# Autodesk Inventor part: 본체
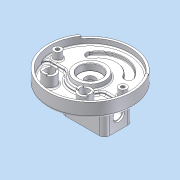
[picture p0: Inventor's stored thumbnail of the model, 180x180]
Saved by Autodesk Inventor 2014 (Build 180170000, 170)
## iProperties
Company: 한국ATC센터
Created: 2015-04
Part Number: 본체
Document SubType Name: Modeling
Designer: KYOUNG IL JANG
Density: 1 g/cm^3
Material: 일반
Mass: 494.771 g
Surface Area: 1387.38 cm^2
Volume: 494.771 cm^3
Appearance: 매끄러움 - 흰색
Author: KYOUNG IL JANG
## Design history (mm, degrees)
sketch "스케치1"
  geometry: L1 (-59, -19)-(-59, 19); L2 (59, 19)-(59, -19); L3 (-41, 19)-(-41, -19); L4 (41, -19)-(41, 19); L5 (38.527, 33.023)-(55.442, 39.179); L6 (-38.527, 33.023)-(-55.442, 39.179); C1 r 90 at (0, 0); C2 r 95 at (0, 0); A1 r 59 centre (0, 19) between (59, 19) and (-59, 19); A2 r 59 centre (0, -19) between (-59, -19) and (59, -19); A3 r 41 centre (0, -19) between (-41, -19) and (41, -19); A4 r 41 centre (0, 19) between (41, 19) and (-41, 19); 2 further points
  constraints: 12 end point, 12 point on circle, 6 centre point, 4 tangent, 2 parallel, 2 point on line, 1 coincident, 1 horizontal alignment, 1 midpoint, 1 vertical, 1 vertical alignment, 3 other
  dimensions: "d2" = 180 diameter of C1; "d3" = 156 dimension on A2 A1; "d4" = 118 distance between parallel lines of L2 L1; "d5" = 18 distance between parallel lines of L2 L4; "d8" = 190 diameter of C2; "d124" = 110 deg dimension on A1.centre point (0, 0) L5.end; "d125" = 140 deg angle of L5 L6
extrude "돌출1" new body sketch "스케치1" distance "d6" = 14; taper "d7" = 0 deg
extrude "돌출2" join sketch "스케치1" distance "d9" = 13; taper "d10" = 0 deg
extrude "돌출3" cut sketch "스케치1" distance "d11" = 7; taper "d12" = 0 deg
sketch "스케치2"
  geometry: C1 r 11.5 at (0, 0); 1 further point
  constraints: 1 centre point, 1 coincident
  dimensions: "d13" = 23 diameter of C1
extrude "돌출4" cut sketch "스케치2" stored distance "d14" = 7; taper "d15" = 0 deg
fillet "모깎기1"
fillet "모깎기2"
sketch "스케치3"
  geometry: L1 (-73.724, 51.622)-(-77.819, 54.49); L2 (73.724, 51.622)-(77.819, 54.49); L3 (0, 0)-(0, -90); A1 r 95 centre (0, 0) between (-77.819, 54.49) and (77.819, 54.49) reference; A2 r 90 centre (0, 0) between (-73.724, 51.622) and (73.724, 51.622) reference; 1 further point
  constraints: 6 end point, 5 point on circle, 1 point on line, 1 vertical, 1 other
  dimensions: "d16" = 250 deg dimension on L2 L1
extrude "돌출5" join sketch "스케치3" distance "d17" = 5; taper "d18" = 0 deg
hole "구멍1" diameter "d21" = 50; stored, may be unused: countersink angle "d25" = 90 deg, drill point angle "d27" = 0 deg; dims "d19" = 10, "d20" = 10, "d22" = 6, "d23" = 4, "d24" = 2, "d26" = 5
fillet "모깎기3" dims "d28" = 0.3
fillet "모깎기5" dims "d30" = 3
sketch "스케치4"
  geometry: C1 r 35 at (0, 0); C2 r 25 at (0, 0); 1 further point
  constraints: 2 centre point, 1 coincident
  dimensions: "d32" = 70 diameter of C1 (derived); "d36" = 10 radial gap between concentric circles of C1 C2
extrude "돌출6" join sketch "스케치4" distance "d33" = 10; taper "d34" = 0 deg
feature "면 기울기2" dims angle "d37" = 10 deg
chamfer "모따기1" distance "d39" = 1; stored, may be unused: second distance "d40" = 2, angle "d41" = 45 deg
fillet "모깎기7" dims "d42" = 5
sketch "스케치5"
  geometry: L1 (-40.249, -12)-(-89.196, -12); L2 (40.249, -12)-(89.196, -12); A1 r 90 centre (0, 0) between (-89.196, -12) and (89.196, -12) reference; A2 r 42 centre (0, 0) between (-40.249, -12) and (40.249, -12); 1 further point
  constraints: 4 end point, 4 point on circle, 1 centre point, 1 collinear, 1 horizontal, 1 point on line
  dimensions: "d43" = 48 radial gap between concentric circles of A1 A2; "d44" = 12 distance from line of point (0, 0) L1
extrude "돌출7" cut sketch "스케치5" stored distance "d45" = 10; taper "d46" = 0 deg
fillet "모깎기8" dims "d47" = 10
chamfer "모따기2" distance "d49" = 1; stored, may be unused: second distance "d50" = 2, angle "d51" = 45 deg
sketch "스케치8"
  geometry: C1 r 9 at (74, 0); C2 r 9 at (-74, 0); A1 r 74 centre (0, 0) between (74, 0) and (-74, 0); 1 further point
  constraints: 3 centre point, 2 horizontal alignment, 2 point on circle, 1 coincident, 1 equal radius
  dimensions: "d64" = 18 diameter of C1; "d65" = 148 diameter of A1
extrude "돌출9" join sketch "스케치8" stored distance "d66" = 5; taper "d67" = 0 deg
sketch "스케치11"
  geometry: C1 r 15 at (40, -52); C2 r 15 at (-40, -52); 1 further point
  constraints: 2 centre point, 1 equal radius, 1 horizontal alignment
  dimensions: "d82" = 52 vertical distance of point (0, 0) C1.centre; "d83" = 30 diameter of C1; "d84" = 80 distance of C2.centre C1.centre; "d85" = 40 horizontal distance of point (0, 0) C1.centre (= 0.5 x d84)
extrude "돌출10" join sketch "스케치11" stored distance "d86" = 10; taper "d87" = 0 deg
node "구멍3"
node "구멍5"
hole "구멍6" diameter "d92" = 20; stored, may be unused: countersink angle "d96" = 90 deg, drill point angle "d98" = 118 deg; dims "d90" = 10, "d91" = 10, "d93" = 6, "d94" = 4, "d95" = 2, "d97" = 8
hole "구멍7" diameter "d101" = 20; stored, may be unused: countersink angle "d105" = 90 deg, drill point angle "d107" = 118 deg; dims "d99" = 10, "d100" = 10, "d102" = 6, "d103" = 4, "d104" = 2, "d106" = 8
fillet "모깎기13" dims "d108" = 3
sketch "스케치13"
  geometry: L1 (-20.252, -58)-(-26, -58); L2 (-42, -58)-(-47.748, -58); L3 (-20.252, -46)-(-26, -46); L4 (-42, -46)-(-47.748, -46); L5 (-108, -65.748)-(-108, -60); L6 (-108, -44)-(-108, -38.252); L7 (-120, -44)-(-120, -38.252); L8 (-120, -60)-(-120, -65.748); A1 r 15 centre (-34, -52) between (-20.252, -58) and (-47.748, -58) reference; A2 r 10 centre (-34, -52) between (-26, -58) and (-42, -58) reference; A3 r 15 centre (-114, -52) between (-108, -65.748) and (-108, -38.252) reference; A4 r 10 centre (-114, -52) between (-108, -60) and (-108, -44) reference; 1 further point
  constraints: 16 end point, 16 point on circle, 3 equal length, 3 point on line, 2 collinear, 1 horizontal, 1 perpendicular
  dimensions: "d114" = 12 distance between parallel lines of L4 L2; "d115" = 6 distance from line of A1.centre L2 (= 0.5 x d114); "d116" = 12 distance between parallel lines of L8 L5 (= d114); "d117" = 6 distance from line of A3.centre L5 (= d115)
extrude "돌출12" join sketch "스케치13" distance "d118" = 3; taper "d119" = 0 deg
fillet "모깎기14" dims "d120" = 1
sketch "스케치14"
  geometry: L1 (23, 32.5)-(-53, 32.5); L2 (-65, 20.5)-(-65, -20.5); L3 (-53, -32.5)-(23, -32.5); L4 (35, -20.5)-(35, 20.5); L5 (30, 20.5)-(30, -20.5); L6 (23, -27.5)-(-53, -27.5); L7 (-60, -20.5)-(-60, 20.5); L8 (-53, 27.5)-(23, 27.5); A1 r 12 centre (-53, -20.5) between (-65, -20.5) and (-53, -32.5); A2 r 12 centre (-53, 20.5) between (-53, 32.5) and (-65, 20.5); A3 r 12 centre (23, 20.5) between (35, 20.5) and (23, 32.5); A4 r 12 centre (23, -20.5) between (23, -32.5) and (35, -20.5); A5 r 7 centre (23, -20.5) between (23, -27.5) and (30, -20.5); A6 r 7 centre (-53, -20.5) between (-60, -20.5) and (-53, -27.5); A7 r 7 centre (-53, 20.5) between (-53, 27.5) and (-60, 20.5); A8 r 7 centre (23, 20.5) between (30, 20.5) and (23, 27.5); A9 r 6 centre (-23, -25) between (-17.546, -27.5) and (-28.454, -27.5); A10 r 6 centre (-23, 25) between (-28.454, 27.5) and (-17.546, 27.5); 6 further points
  constraints: 20 point on circle, 16 end point, 12 point on line, 10 centre point, 8 tangent, 4 equal radius, 4 parallel, 2 perpendicular, 1 horizontal, 1 horizontal alignment, 1 midpoint, 1 vertical alignment, 7 other
  dimensions: "d126" = 35 distance from line of point (0, 0) L4; "d127" = 65 distance of point (35, -32.5) point (35, 32.5); "d128" = 100 distance of point (35, 32.5) point (-65, 32.5); "d132" = 12 radius of A1; "d133" = 5 distance between parallel lines of L5 L4; "d141" = 42 distance from line of A9.centre L2; "d142" = 12 diameter of A9; "d143" = 50 distance of A10.centre A9.centre; "d144" = 25 vertical distance of point (0, 0) A9.centre (= 0.5 x d143)
extrude "돌출13" join sketch "스케치14" distance "d130" = 58; taper "d131" = 0 deg
fillet "모깎기16" dims "d145" = 3
hole "구멍8" diameter "d148" = 4.134; stored, may be unused: countersink angle "d152" = 90 deg, drill point angle "d154" = 118 deg; dims "d146" = 10, "d147" = 10, "d149" = 12, "d150" = 4, "d151" = 2, "d153" = 15
hole "구멍9" diameter "d157" = 4.134; stored, may be unused: countersink angle "d161" = 90 deg, drill point angle "d163" = 118 deg; dims "d155" = 10, "d156" = 10, "d158" = 12, "d159" = 4, "d160" = 2, "d162" = 15
sketch "스케치17"
  geometry: L1 (-58, 110.5)-(-58, -69.5) reference; C1 r 15 at (-29.5, 20.5); 1 further point
  constraints: 1 centre point, 1 horizontal alignment
  dimensions: "d164" = 28.5 distance from line of C1.centre L1; "d165" = 30 diameter of C1
extrude "돌출16" join sketch "스케치17" distance "d166" = 28; taper "d167" = 0 deg
fillet "모깎기17" dims "d168" = 1
hole "구멍10" diameter "d171" = 22; stored, may be unused: countersink angle "d175" = 90 deg, drill point angle "d177" = 118 deg; dims "d169" = 10, "d170" = 10, "d172" = 12, "d173" = 26, "d174" = 4, "d176" = 15
node "솔리드1"
sketch "스케치9"
  geometry: 1 further point
hole "구멍2" sketch "스케치9" diameter "d68" = 8.376; stored, may be unused: countersink angle "d72" = 90 deg, drill point angle "d74" = 120 deg; dims "d69" = 16, "d70" = 4, "d71" = 2, "d73" = 21
sketch "스케치10"
  geometry: 1 further point
hole "구멍4" sketch "스케치10" diameter "d75" = 8.376; stored, may be unused: countersink angle "d79" = 90 deg, drill point angle "d81" = 120 deg; dims "d76" = 16, "d77" = 4, "d78" = 2, "d80" = 21
